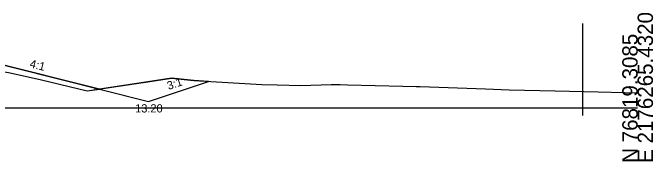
# Model space of a CAD drawing. Extents: x 2177029 to 2201446, y 59897 to 78390.
# Drawn here: x 2199328.6 to 2199445.6, y 67397.6 to 67424.6 of the extents above; entities that cross this region are included whole.
import ezdxf

# ---------------------------------------------------------------- set-up
doc = ezdxf.new("R2010")
doc.units = 0
for name, color, linetype in [('Exist Cross Section Cell', 7, 'Continuous'), ('Exist PHM Roadway Shape', 7, 'Continuous'), ('Exist XS Ground Line', 7, 'Continuous'), ('Prop CMT Guardrail Widen Shoulder', 7, 'Continuous'), ('Prop CMT Top Wall Envelope', 7, 'Continuous'), ('Prop Hatching', 7, 'Continuous'), ('Prop XS Side Slope Text', 7, 'Continuous'), ('Scratch_Level_2', 7, 'Continuous')]:
    doc.layers.add(name, color=color, linetype=linetype)

msp = doc.modelspace()

# ---------------------------------------------------------------- linework, layer by layer
at = {"layer": 'Exist Cross Section Cell'}
msp.add_line((2199242.73, 67407.31), (2199442.73, 67407.31), dxfattribs=at)
at = {"layer": 'Exist XS Ground Line'}
msp.add_lwpolyline([(2199328.15, 67413.7), (2199333.87, 67412.43), (2199342.22, 67410.41), (2199354.06, 67412.21), (2199357.59, 67412.72), (2199361.71, 67412.31), (2199374.11, 67411.58), (2199376.93, 67411.55), (2199381.23, 67411.43), (2199386.77, 67411.59), (2199388.43, 67411.56), (2199389.72, 67411.54), (2199399.84, 67411.31), (2199402.29, 67411.24), (2199403.01, 67411.22), (2199414.97, 67410.79), (2199419.27, 67410.63), (2199427.65, 67410.41), (2199435.53, 67410.23), (2199440.33, 67410.13), (2199442.73, 67410.1)], dxfattribs=at)
at = {"layer": 'Prop Hatching'}
msp.add_line((2199353.42, 67408.51), (2199364.36, 67412.16), dxfattribs=at)
msp.add_lwpolyline([(2199318.74, 67416.68), (2199320.74, 67416.68), (2199353.42, 67408.51)], dxfattribs=at)
at = {"layer": 'Prop XS Side Slope Text'}
for points in [[(2199342.22, 67410.41), (2199344.46, 67410.75), (2199324.74, 67415.68), (2199319.74, 67415.68), (2199311.92, 67415.68), (2199313.07, 67415.63), (2199318.55, 67415.49), (2199328.15, 67413.7), (2199333.87, 67412.43)], [(2199353.42, 67408.51), (2199364.36, 67412.16), (2199361.71, 67412.31), (2199357.59, 67412.72), (2199354.06, 67412.21), (2199344.46, 67410.75)]]:
    msp.add_lwpolyline(points, close=True, dxfattribs=at)
at = {"layer": 'Scratch_Level_2'}
msp.add_line((2199432.73, 67405.94), (2199432.73, 67422.68), dxfattribs=at)

# ---------------------------------------------------------------- texts
at = {"layer": 'Exist Cross Section Cell'}
for s, p in [('E 2176265.4320', (2199445.53, 67397.31)), ('N 76819.3085', (2199442.73, 67397.31))]:
    msp.add_text(s, height=2.8, rotation=90, dxfattribs=at).set_placement(p)
at = {"layer": 'Exist PHM Roadway Shape'}
msp.add_text('RT_Slope_Fill', height=0.2, dxfattribs=at).set_placement((2199343.51, 67410.65))
at = {"layer": 'Prop CMT Guardrail Widen Shoulder'}
msp.add_text('4:1', height=1.5, rotation=345.9648, dxfattribs=at).set_placement((2199331.63, 67414.73))
at = {"layer": 'Prop CMT Top Wall Envelope'}
msp.add_text('3:1', height=1.5, rotation=18.4349, dxfattribs=at).set_placement((2199357.09, 67410.59))
msp.add_text('13.20', height=1.5, dxfattribs=at).set_placement((2199350.97, 67406.49))

doc.saveas('drawing.dxf')
